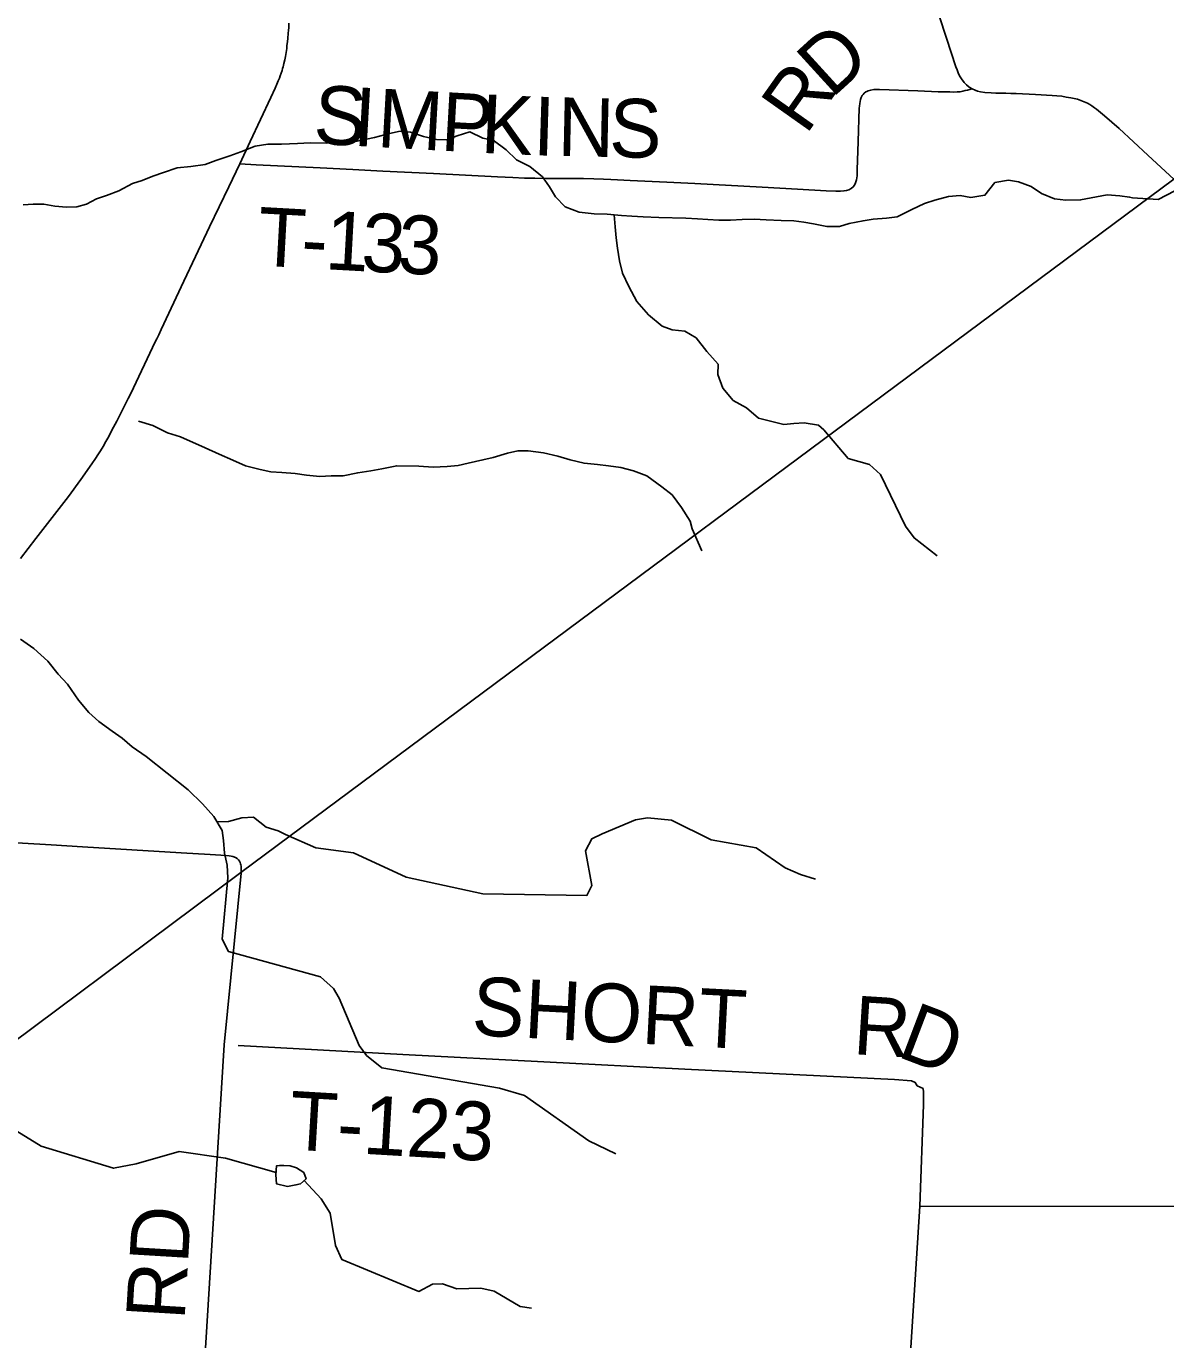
# Model space of a CAD drawing. Extents: x 0 to 48.6, y 0 to 22.
# Drawn here: x 4.415 to 5.519, y 15.882 to 17.154 of the extents above; entities that cross this region are included whole.
import ezdxf

# ---------------------------------------------------------------- set-up
doc = ezdxf.new("R2010")
doc.units = 0
for name, color, linetype in [('GM_X_Corporation', 7, 'Continuous'), ('GM_X_County_Road', 7, 'Continuous'), ('GM_X_Minor_Lake', 7, 'Continuous'), ('GM_X_Minor_River', 7, 'Continuous'), ('GM_X_State_Route', 7, 'Continuous'), ('GM_X_Township_Road', 7, 'Continuous'), ('GM_X_Township_Road_Text', 7, 'Continuous')]:
    doc.layers.add(name, color=color, linetype=linetype)

msp = doc.modelspace()

# ---------------------------------------------------------------- linework, layer by layer
at = {"layer": 'GM_X_Corporation'}
msp.add_lwpolyline([(5.0944, 14.1), (8.9, 14.1), (8.9, 19.5692), (8.5348, 19.2897), (7.2261, 18.2847), (6.9471, 18.0777), (6.5365, 17.7727), (5.8387, 17.2541), (5.5264, 17.0064), (4.6225, 16.3345), (4.044, 15.9033), (4.0346, 15.8959), (4.0398, 15.887), (4.3544, 15.3539), (4.4679, 15.1616), (4.7542, 14.6766)], close=True, dxfattribs=at)
msp.add_lwpolyline([(3.9507, 15.8348), (4.0346, 15.8959), (4.044, 15.9033), (4.6225, 16.3345), (5.5264, 17.0064)], dxfattribs=at)
msp.add_lwpolyline([(3.9507, 15.8348), (4.0346, 15.8959), (4.044, 15.9033), (4.6225, 16.3345), (5.5264, 17.0064)], dxfattribs=at)
at = {"layer": 'GM_X_County_Road'}
for points in [[(4.2332, 16.374), (4.2422, 16.3734), (4.2856, 16.3708), (4.383, 16.3648), (4.4388, 16.3613), (4.4692, 16.3596), (4.5648, 16.3537), (4.5927, 16.3521), (4.6032, 16.3514), (4.6112, 16.3509), (4.6131, 16.3506), (4.6149, 16.3501), (4.6172, 16.3493), (4.6188, 16.3483), (4.6201, 16.347), (4.6212, 16.3455), (4.6217, 16.3444), (4.6221, 16.3432), (4.6224, 16.3421), (4.6228, 16.3408), (4.6229, 16.3381), (4.6228, 16.334)], [(4.6086, 15.1588), (4.64, 15.1582), (4.8348, 15.1585), (4.9035, 15.1586), (4.9331, 15.1596), (5.071, 15.181), (5.1203, 15.1895), (5.1743, 15.1992), (5.2077, 15.2059), (5.2218, 15.2088), (5.2271, 15.216), (5.2317, 15.2361), (5.2617, 15.7172), (5.2803, 16.0116), (5.7212, 16.011), (6.0742, 16.1743), (6.2545, 16.2661)]]:
    msp.add_lwpolyline(points, dxfattribs=at)
at = {"layer": 'GM_X_Minor_Lake'}
for points in [[(4.6565, 16.0417), (4.6572, 16.033), (4.6678, 16.0306), (4.6758, 16.032), (4.6803, 16.0331), (4.6857, 16.0379), (4.6835, 16.044), (4.6764, 16.0487), (4.6703, 16.0506), (4.6643, 16.0507), (4.66, 16.0508)], [(4.66, 16.0508), (4.6569, 16.0504), (4.6565, 16.0417)]]:
    msp.add_lwpolyline(points, dxfattribs=at)
at = {"layer": 'GM_X_Minor_River'}
for points in [[(5.4863, 16.9882), (5.5112, 16.9867), (5.544, 17.0038), (5.5562, 17.004), (5.5795, 16.9882), (5.5999, 16.9511), (5.6104, 16.9408), (5.6315, 16.9329), (5.6445, 16.9354), (5.6662, 16.9469), (5.6924, 16.9481), (5.7061, 16.9514), (5.721, 16.9595), (5.7644, 17.0277), (5.7866, 17.046), (5.8, 17.0542), (5.8225, 17.0642)], [(4.4115, 16.9815), (4.4214, 16.9822), (4.4316, 16.982), (4.4423, 16.98), (4.4536, 16.9791), (4.4635, 16.9793), (4.473, 16.9819), (4.4826, 16.9871), (4.4925, 16.9903), (4.5044, 16.9951), (4.5174, 17.0022), (4.5269, 17.0051), (4.5372, 17.0091), (4.5475, 17.0128), (4.5609, 17.0172), (4.5742, 17.0185), (4.5879, 17.0206), (4.5982, 17.0243), (4.6119, 17.0287), (4.6226, 17.0327), (4.6364, 17.0382), (4.6486, 17.04), (4.6618, 17.0402), (4.6774, 17.0407), (4.6896, 17.0413), (4.7052, 17.0411), (4.7158, 17.0414), (4.7321, 17.0423), (4.752, 17.0466), (4.7664, 17.0506), (4.7767, 17.0527), (4.787, 17.0518), (4.7994, 17.0475), (4.8119, 17.0447), (4.8218, 17.0442), (4.8321, 17.0482), (4.8443, 17.0522), (4.8568, 17.046), (4.867, 17.044), (4.8794, 17.0347), (4.8895, 17.0251), (4.9024, 17.0184), (4.9148, 17.0084), (4.9215, 16.9988), (4.9274, 16.9893), (4.9368, 16.9793), (4.9504, 16.9742), (4.9648, 16.9728), (4.9773, 16.9723), (4.9914, 16.971), (5.0012, 16.9705), (5.0122, 16.9699), (5.0274, 16.969), (5.0536, 16.9686), (5.065, 16.9677), (5.0749, 16.9672), (5.0855, 16.9667), (5.0969, 16.9666), (5.1083, 16.9672), (5.1197, 16.9674), (5.1315, 16.9669), (5.1459, 16.9663), (5.1584, 16.9658), (5.1679, 16.9645), (5.1774, 16.9629), (5.1903, 16.9604), (5.2024, 16.9603), (5.2119, 16.9632), (5.2253, 16.966), (5.2352, 16.9674), (5.2481, 16.9684), (5.2584, 16.9698), (5.2725, 16.9768), (5.2848, 16.9827), (5.2947, 16.986), (5.308, 16.9896), (5.3194, 16.9903), (5.3297, 16.9886), (5.3434, 16.9907), (5.353, 17.0031), (5.3663, 17.0052), (5.3758, 17.0036), (5.3883, 16.9992), (5.3981, 16.9923), (5.4109, 16.9872), (5.4219, 16.9859), (5.436, 16.9861), (5.4619, 16.9911), (5.474, 16.9902)], [(5.474, 16.9902), (5.4835, 16.9889), (5.4863, 16.9882)], [(4.9843, 16.9716), (4.9851, 16.96), (4.9861, 16.9494), (4.9875, 16.9395), (4.9893, 16.927), (4.9921, 16.9152), (4.9984, 16.9022), (5.0062, 16.8876), (5.0174, 16.875), (5.0306, 16.8638), (5.0404, 16.8602), (5.0525, 16.8589), (5.0635, 16.8527), (5.0739, 16.8393), (5.0848, 16.827), (5.0846, 16.8172), (5.0894, 16.8038), (5.0995, 16.7919), (5.1123, 16.7849), (5.1239, 16.7749), (5.1345, 16.7721), (5.1486, 16.7685), (5.1584, 16.7695), (5.1683, 16.7701), (5.182, 16.7681), (5.1874, 16.7635)], [(5.0596, 16.6675), (5.0577, 16.6751), (5.0495, 16.6882), (5.0405, 16.7004), (5.0304, 16.7081), (5.0157, 16.719), (5.0029, 16.7237), (4.9907, 16.7269), (4.9786, 16.7286), (4.968, 16.7298), (4.9551, 16.7311), (4.9415, 16.7344), (4.9297, 16.7379), (4.9157, 16.7411), (4.9009, 16.7432), (4.8907, 16.743), (4.8808, 16.7408), (4.8671, 16.7368), (4.8571, 16.7343), (4.8427, 16.7311), (4.8331, 16.7289), (4.8225, 16.7279), (4.8088, 16.7273), (4.7948, 16.7283), (4.7735, 16.7286), (4.759, 16.7257), (4.7484, 16.7236), (4.7358, 16.7218), (4.7217, 16.719), (4.7099, 16.7188), (4.6989, 16.7181), (4.686, 16.7194), (4.675, 16.7211), (4.6621, 16.722), (4.6515, 16.7229), (4.6413, 16.725), (4.6269, 16.7286), (4.6148, 16.734), (4.6016, 16.7399), (4.588, 16.7461), (4.5642, 16.7567), (4.5514, 16.7607), (4.5374, 16.7677), (4.5234, 16.7717)], [(5.1874, 16.7635), (5.2109, 16.7358), (5.2314, 16.7298), (5.2422, 16.7202), (5.2663, 16.6702), (5.2748, 16.6587), (5.297, 16.6414)], [(5.0596, 16.6675), (5.0691, 16.6464)], [(4.4089, 16.5606), (4.4221, 16.5517), (4.4356, 16.5393), (4.4456, 16.5267), (4.4546, 16.5171), (4.4651, 16.5017), (4.4752, 16.4895), (4.4849, 16.481), (4.4977, 16.4717), (4.5075, 16.4647), (4.5172, 16.4563), (4.5308, 16.447), (4.5714, 16.4146), (4.5853, 16.4011), (4.5965, 16.3888), (4.6043, 16.3754), (4.6057, 16.3655), (4.6066, 16.3534), (4.6091, 16.3419), (4.61, 16.3294)], [(4.5995, 16.3836), (4.6105, 16.3841), (4.6234, 16.3877), (4.6348, 16.3883), (4.6472, 16.3787), (4.6586, 16.3751), (4.6658, 16.3714)], [(4.6658, 16.3714), (4.6951, 16.3584), (4.7318, 16.3538), (4.7828, 16.33), (4.8569, 16.314), (4.9578, 16.3124), (4.9625, 16.3222), (4.9565, 16.3556), (4.9627, 16.3673), (4.9726, 16.3721), (5.0047, 16.3858), (5.0164, 16.3875), (5.0396, 16.3854), (5.078, 16.3663), (5.1219, 16.3586), (5.1497, 16.3393), (5.1648, 16.3326), (5.1792, 16.3283)], [(4.61, 16.3294), (4.6044, 16.27), (4.6107, 16.2581), (4.6996, 16.2335), (4.7123, 16.2224), (4.7179, 16.2128), (4.7371, 16.1671), (4.7441, 16.1575), (4.7592, 16.1456), (4.8731, 16.1256), (4.8973, 16.1188), (4.9597, 16.0748), (4.9857, 16.062)], [(4.3441, 16.1296), (4.3797, 16.1069), (4.4056, 16.0842), (4.4289, 16.0695), (4.4992, 16.0481), (4.5212, 16.0524), (4.5628, 16.0645), (4.6078, 16.0578), (4.6567, 16.044)], [(4.6839, 16.0363), (4.7003, 16.0184), (4.7092, 16.0046), (4.7141, 15.9735), (4.7204, 15.9597), (4.7951, 15.9289), (4.8081, 15.9359), (4.818, 15.9362), (4.8319, 15.9314), (4.8551, 15.9319), (4.8679, 15.9291), (4.8932, 15.9144), (4.9042, 15.9127)]]:
    msp.add_lwpolyline(points, dxfattribs=at)
at = {"layer": 'GM_X_State_Route'}
for points in [[(5.2947, 17.1775), (5.3052, 17.1456), (5.3115, 17.1261), (5.3143, 17.1179), (5.3153, 17.1151), (5.3164, 17.1121), (5.3176, 17.1093), (5.3189, 17.1064), (5.3208, 17.1033), (5.3233, 17.0999), (5.3254, 17.0977), (5.3281, 17.0954), (5.331, 17.0938), (5.3338, 17.0924), (5.3362, 17.0916), (5.3391, 17.091), (5.3433, 17.0903), (5.3494, 17.0899), (5.3541, 17.0897), (5.3591, 17.0895), (5.3637, 17.0894), (5.3685, 17.0892), (5.3737, 17.0891), (5.3923, 17.0884), (5.4085, 17.0873), (5.4131, 17.0869), (5.4178, 17.0865), (5.422, 17.0858), (5.4265, 17.0851), (5.4299, 17.0843), (5.4332, 17.0836), (5.438, 17.0819), (5.4426, 17.0799), (5.4449, 17.0785), (5.447, 17.0773), (5.4495, 17.0754), (5.4516, 17.074), (5.4593, 17.0675), (5.4733, 17.0552), (5.5011, 17.0294), (5.5267, 17.0058)], [(4.4091, 16.6388), (4.4238, 16.6581), (4.4554, 16.6988), (4.4676, 16.7153), (4.4783, 16.7305), (4.4816, 16.7356), (4.4841, 16.7393), (4.4865, 16.7432), (4.489, 16.7472), (4.4917, 16.7521), (4.4945, 16.7569), (4.4963, 16.7604), (4.4992, 16.7659), (4.5023, 16.7717), (4.5124, 16.7918), (4.5135, 16.7939), (4.5158, 16.7988), (4.5396, 16.8486), (4.541, 16.8516), (4.5429, 16.8555), (4.5453, 16.8607), (4.5673, 16.9073), (4.5787, 16.9314), (4.5922, 16.9601), (4.6109, 16.9987), (4.6214, 17.0211), (4.6314, 17.0426), (4.6517, 17.0852), (4.6558, 17.0944), (4.6575, 17.0983), (4.6588, 17.1015), (4.6598, 17.104), (4.6607, 17.1063), (4.6615, 17.109), (4.6624, 17.1115), (4.663, 17.1133), (4.6635, 17.1151), (4.6643, 17.1183), (4.6651, 17.1217), (4.6657, 17.1252), (4.6664, 17.129), (4.6669, 17.1329), (4.6672, 17.1356), (4.6677, 17.1394), (4.668, 17.1427), (4.6684, 17.1474), (4.6687, 17.1507), (4.6689, 17.153), (4.6691, 17.1574)]]:
    msp.add_lwpolyline(points, dxfattribs=at)
at = {"layer": 'GM_X_Township_Road'}
for points in [[(4.6214, 17.0211), (4.6373, 17.0203), (4.6994, 17.0172), (4.731, 17.0156), (4.7601, 17.014), (4.8092, 17.0118), (4.8712, 17.0084), (4.8859, 17.0078), (4.8973, 17.0073), (4.9074, 17.0071), (4.9184, 17.0069), (4.9278, 17.0069), (4.9544, 17.0068), (4.9644, 17.0065), (4.9737, 17.0063), (4.9809, 17.0059), (4.9873, 17.0056), (4.9934, 17.0053), (4.9997, 17.0049), (5.0351, 17.0033), (5.0624, 17.0019), (5.1276, 16.9984), (5.1617, 16.9966), (5.1896, 16.9951), (5.1989, 16.9945), (5.2033, 16.9945), (5.2068, 16.9948), (5.2094, 16.9953), (5.2116, 16.996), (5.2138, 16.9973), (5.2158, 16.9988), (5.2171, 17.0006), (5.2181, 17.0027), (5.219, 17.0056), (5.2195, 17.0096), (5.2197, 17.0154), (5.2207, 17.0427), (5.2217, 17.075), (5.2219, 17.0771), (5.2221, 17.0794), (5.2224, 17.0816), (5.2229, 17.0834), (5.2235, 17.0852), (5.2245, 17.0872), (5.2253, 17.0884), (5.2263, 17.0895), (5.2279, 17.0908), (5.2289, 17.0913), (5.2302, 17.0919), (5.2327, 17.0926), (5.2357, 17.0931), (5.2412, 17.093), (5.2785, 17.0918), (5.2981, 17.0909), (5.3015, 17.0907), (5.3046, 17.0907), (5.3094, 17.0907), (5.3127, 17.0906), (5.3166, 17.0908), (5.3195, 17.091), (5.3219, 17.0915), (5.3242, 17.0921), (5.3266, 17.0926), (5.331, 17.0938)], [(4.3546, 15.3464), (4.3547, 15.3533), (4.3551, 15.3891), (4.3552, 15.4107), (4.356, 15.4202), (4.356, 15.4263), (4.3572, 15.4286), (4.3598, 15.4308), (4.3712, 15.4315), (4.5515, 15.4224), (4.5587, 15.4243), (4.5614, 15.4337), (4.587, 15.853), (4.6064, 16.1678), (4.6228, 16.334)], [(4.62, 16.1671), (4.7795, 16.1584), (5.0527, 16.1443), (5.2558, 16.1343), (5.2721, 16.1327), (5.2759, 16.1312), (5.2778, 16.1281), (5.2834, 16.1254), (5.2838, 16.122), (5.2838, 16.1095), (5.2803, 16.0116)]]:
    msp.add_lwpolyline(points, dxfattribs=at)

# ---------------------------------------------------------------- texts
at = {"layer": 'GM_X_Township_Road_Text'}
for s, height, rotation, p in [('D', 0.0568, 42.3563, (5.1947, 17.0837)), ('R', 0.0568, 54.7391, (5.1699, 17.0481)), ('S', 0.0568, 356.7817, (4.6921, 17.0409)), ('I', 0.0568, 356.7889, (4.7304, 17.0387)), ('M', 0.0568, 356.7848, (4.7536, 17.0374)), ('P', 0.0568, 356.8103, (4.8152, 17.034)), ('K', 0.0568, 357.4104, (4.8542, 17.0318)), ('I', 0.0568, 358.2395, (4.905, 17.0295)), ('N', 0.0568, 358.7782, (4.9289, 17.0288)), ('S', 0.0568, 358.8595, (4.979, 17.0277)), ('T', 0.0568, 356.8313, (4.6376, 16.9227)), ('1', 0.0568, 356.8457, (4.7033, 16.9191)), ('3', 0.0568, 356.8975, (4.7383, 16.9172)), ('3', 0.0568, 357.133, (4.7736, 16.9153)), ('-', 0.0568, 356.833, (4.68, 16.9204)), ('SHORT', 0.05682, 357.0749, (4.8455, 16.1772)), ('R', 0.0568, 356.3874, (5.2148, 16.1588)), ('D', 0.0568, 339.17, (5.257, 16.1569)), ('T-123', 0.05682, 356.6342, (4.6682, 16.0665)), ('RD', 0.05682, 86.5466, (4.5679, 15.9004))]:
    msp.add_text(s, height=height, rotation=rotation, dxfattribs=at).set_placement(p)

doc.saveas('drawing.dxf')
